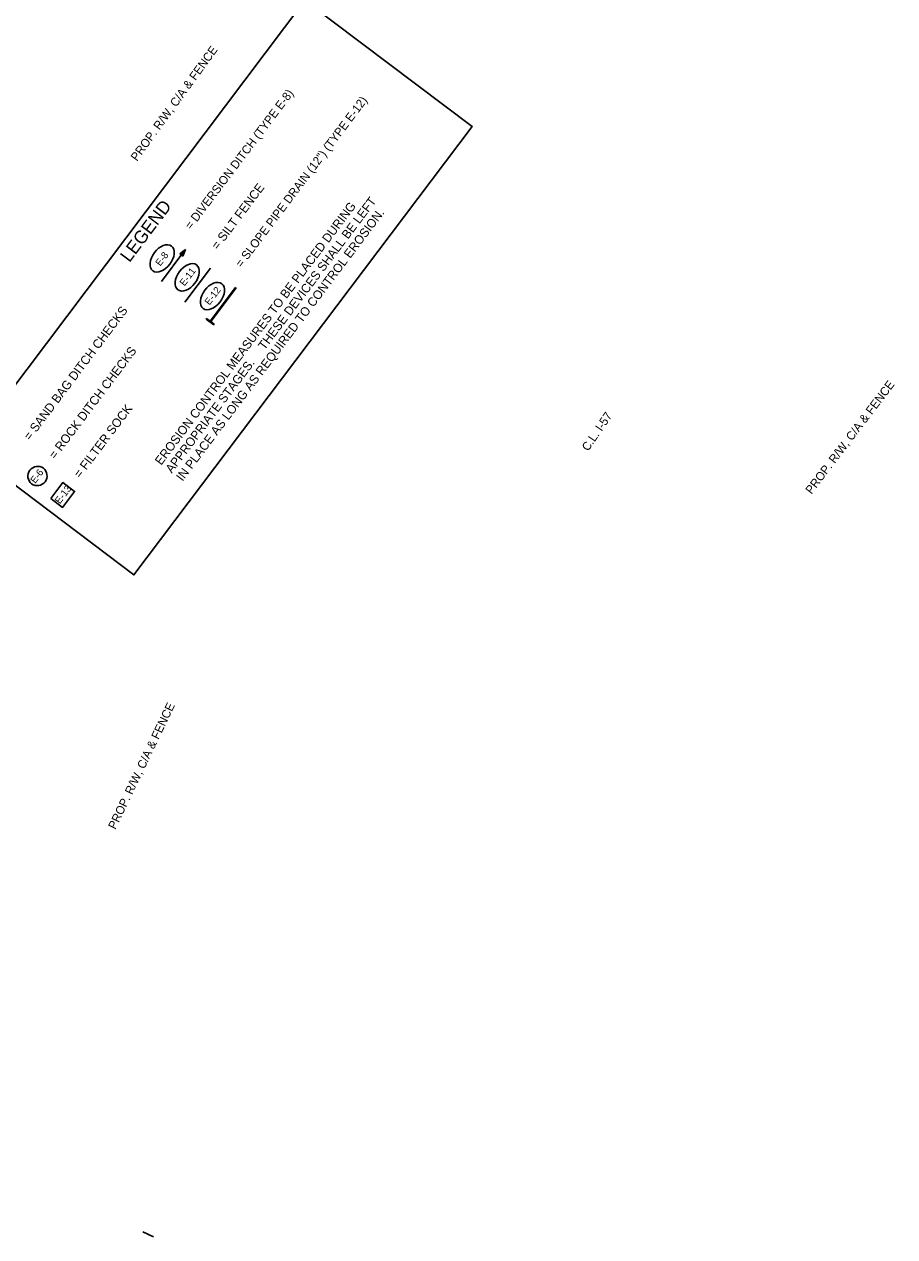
# Model space of a CAD drawing. Extents: x 1713751 to 1715480, y 763628 to 765350.
# Drawn here: x 1714378 to 1714993, y 763628 to 764484 of the extents above; entities that cross this region are included whole.
import ezdxf

# ---------------------------------------------------------------- set-up
doc = ezdxf.new("R2010")
doc.units = 0
for name, color, linetype in [('1', 7, 'Continuous'), ('Default', 7, 'Continuous'), ('Level 1', 7, 'Continuous'), ('Level 44', 7, 'Continuous'), ('R_Draft', 7, 'Continuous')]:
    doc.layers.add(name, color=color, linetype=linetype)

msp = doc.modelspace()

# ---------------------------------------------------------------- linework, layer by layer
at = {"layer": '1'}
for points in [[(1714337.84, 764184.32), (1714576.55, 764501.1), (1714694.66, 764412.1), (1714455.95, 764095.31)], [(1714397.18, 764149.37), (1714405.62, 764160.57), (1714414.01, 764154.25), (1714405.57, 764143.05)]]:
    msp.add_lwpolyline(points, close=True, dxfattribs=at)
at = {"layer": 'Default'}
msp.add_line((1714469.68, 763627.97), (1714462.1, 763631.41), dxfattribs=at)
at = {"layer": 'Level 1'}
for p, q in [((1714492.26, 764325.14), (1714488.22, 764322.17)), ((1714488.22, 764322.17), (1714490.52, 764320.43)), ((1714491.29, 764324.31), (1714488.51, 764321.96)), ((1714491.35, 764324.25), (1714488.8, 764321.74)), ((1714491.42, 764324.18), (1714489.08, 764321.53)), ((1714489.66, 764321.09), (1714491.58, 764324.07)), ((1714489.94, 764320.87), (1714491.65, 764324.01)), ((1714490.24, 764320.65), (1714491.74, 764323.98)), ((1714490.52, 764320.43), (1714492.26, 764325.14))]:
    msp.add_line(p, q, dxfattribs=at)
msp.add_lwpolyline([(1714475.3, 764302.63), (1714491.24, 764323.79)], dxfattribs=at)
for centre, major_axis, ratio in [((1714475.82, 764318.82), (6.59, 8.75), 0.622952), ((1714493.54, 764305.5), (6.59, 8.76), 0.622952), ((1714511.35, 764292.24), (6.59, 8.75), 0.622952), ((1714387.81, 764165.19), (-4.14, -5.5), 0.97521)]:
    msp.add_ellipse(centre, major_axis=major_axis, ratio=ratio, dxfattribs=at)
at = {"layer": 'Level 44'}
for p, q in [((1714527.67, 764298.4), (1714509.69, 764274.54)), ((1714528.07, 764298.1), (1714510.09, 764274.24)), ((1714527.67, 764298.4), (1714528.07, 764298.1)), ((1714506.91, 764276.02), (1714507.21, 764276.41)), ((1714509.69, 764274.54), (1714507.21, 764276.41)), ((1714512.27, 764271.97), (1714506.91, 764276.02)), ((1714512.58, 764272.37), (1714510.09, 764274.24)), ((1714512.27, 764271.97), (1714512.58, 764272.37))]:
    msp.add_line(p, q, dxfattribs=at)
msp.add_lwpolyline([(1714491.95, 764287.85), (1714510.05, 764311.93)], dxfattribs=at)

# ---------------------------------------------------------------- texts
at = {"layer": '1'}
msp.add_text('E-13', height=4.999, rotation=52.61773, dxfattribs=at).set_placement((1714403.58, 764145.05))
at = {"layer": 'Level 1'}
for s, height, rotation, p in [('= DIVERSION DITCH (TYPE E-8)', 6, 53.00001, (1714496.15, 764338.74)), ('= SLOPE PIPE DRAIN (12") (TYPE E-12)', 6, 53.00001, (1714531.79, 764311.88)), ('= SILT FENCE', 6.25, 53.058, (1714515.06, 764324.49)), ('THESE DEVICES SHALL BE LEFT', 6.25, 53.058, (1714548.11, 764253.73)), ('EROSION CONTROL MEASURES TO BE PLACED DURING', 6.25, 53.058, (1714475.17, 764172.38)), ('IN PLACE AS LONG AS REQUIRED TO CONTROL EROSION.', 6.25, 53.058, (1714490.21, 764161.07)), ('E-8', 4.876, 53.00001, (1714474.51, 764313.03)), ('E-11 ', 4.876, 53.058, (1714491.62, 764298.95)), ('E-12', 4.876, 53.00001, (1714509.27, 764285.47)), ('= SAND BAG DITCH CHECKS', 6.25, 53.058, (1714382.52, 764189.85)), ('= ROCK DITCH CHECKS', 6.25, 53.058, (1714400.24, 764176.52)), ('APPROPRIATE STAGES. ', 6.25, 53.058, (1714482.69, 764166.72)), ('= FILTER SOCK', 6.25, 53.00001, (1714417.86, 764163.24)), ('E-6 ', 4.876, 53.058, (1714386.25, 764159.57))]:
    msp.add_text(s, height=height, rotation=rotation, dxfattribs=at).set_placement(p)
at = {"layer": 'Level 44'}
msp.add_text('LEGEND', height=9.143, rotation=53.058, dxfattribs=at).set_placement((1714452.76, 764315.51))
at = {"layer": 'R_Draft'}
for s, rotation, p in [('PROP. R/W, C/A & FENCE', 54.05542, (1714458.01, 764387.07)), ('PROP. R/W, C/A & FENCE', 52.82577, (1714934.27, 764151.94)), ('C.L. I-57', 55.78633, (1714776.6, 764182.26)), ('PROP. R/W, C/A & FENCE', 64.42816, (1714442.84, 763915.19))]:
    msp.add_text(s, height=6, rotation=rotation, dxfattribs=at).set_placement(p)

doc.saveas('drawing.dxf')
